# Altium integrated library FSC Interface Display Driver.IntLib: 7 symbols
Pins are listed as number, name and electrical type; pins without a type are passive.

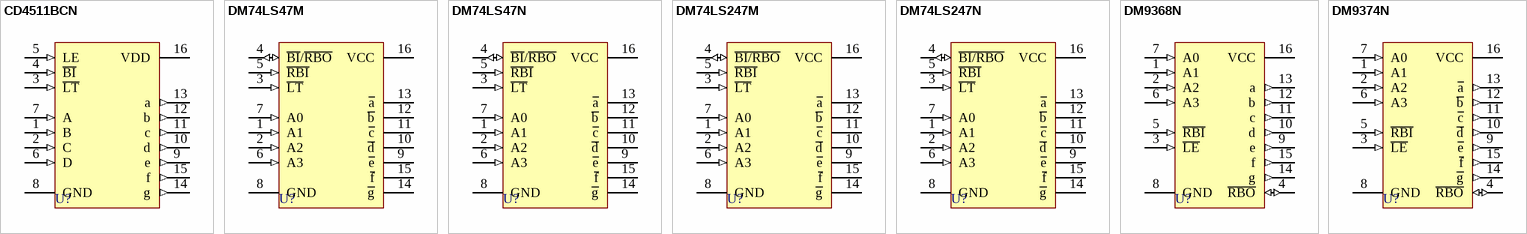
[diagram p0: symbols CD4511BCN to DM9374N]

## CD4511BCN
designator U?
BCD-to-7 Segment Latch/Decoder/Driver
footprint N16E (DIP; 16 Leads; Row Spacing 7.62 mm; Pitch 2.54 mm)
3D model N16E (DIP; 16 Leads; Row Spacing 7.62 mm; Pitch 2.54 mm)
simulation model 4511 (SIMCODE)
pins: 1 B (in), 2 C (in), 3 ~{LT} (in), 4 ~{BI} (in), 5 LE (in), 6 D (in), 7 A (in), 8 GND (power), 9 e (out), 10 d (out), 11 c (out), 12 b (out), 13 a (out), 14 g (out), 15 f (out), 16 VDD (power)

## DM74LS47M
designator U?
BCD to 7-Segment Decoder/Driver with Open-Collector Output
footprint M16A_N (SOIC, 16-Leads, Body 9.9x3.9mm, Pitch 1.27mm, IPC Medium Density)
footprint M16A_L (SOIC, 16-Leads, Body 9.9x3.9mm, Pitch 1.27mm, IPC High Density)
footprint M16A_M (SOIC, 16-Leads, Body 9.9x3.9mm, Pitch 1.27mm, IPC Low Density)
3D model M16A (16-Pin Small Outline Integrated Circuit 1.27 mm Pitch)
signal-integrity model DM74LS47M
pins: 1 A1 (in), 2 A2 (in), 3 ~{LT} (in), 4 ~{BI}/~{RBO} (io), 5 ~{RBI} (in), 6 A3 (in), 7 A0 (in), 8 GND (power), 9 ~{e} (oc), 10 ~{d} (oc), 11 ~{c} (oc), 12 ~{b} (oc), 13 ~{a} (oc), 14 ~{g} (oc), 15 ~{f} (oc), 16 VCC (power)

## DM74LS47N
designator U?
BCD to 7-Segment Decoder/Driver with Open-Collector Output
footprint N16E (DIP; 16 Leads; Row Spacing 7.62 mm; Pitch 2.54 mm)
3D model N16E (DIP; 16 Leads; Row Spacing 7.62 mm; Pitch 2.54 mm)
simulation model 74LS47 (SIMCODE)
signal-integrity model DM74LS47N
pins: 1 A1 (in), 2 A2 (in), 3 ~{LT} (in), 4 ~{BI}/~{RBO} (io), 5 ~{RBI} (in), 6 A3 (in), 7 A0 (in), 8 GND (power), 9 ~{e} (oc), 10 ~{d} (oc), 11 ~{c} (oc), 12 ~{b} (oc), 13 ~{a} (oc), 14 ~{g} (oc), 15 ~{f} (oc), 16 VCC (power)

## DM74LS247M
designator U?
BCD to 7-Segment Decoder/Driver with Open-Collector Output
footprint M16A_N (SOIC, 16-Leads, Body 9.9x3.9mm, Pitch 1.27mm, IPC Medium Density)
footprint M16A_L (SOIC, 16-Leads, Body 9.9x3.9mm, Pitch 1.27mm, IPC High Density)
footprint M16A_M (SOIC, 16-Leads, Body 9.9x3.9mm, Pitch 1.27mm, IPC Low Density)
3D model M16A (16-Pin Small Outline Integrated Circuit 1.27 mm Pitch)
signal-integrity model DM74LS247M
pins: 1 A1 (in), 2 A2 (in), 3 ~{LT} (in), 4 ~{BI/RBO} (io), 5 ~{RBI} (in), 6 A3 (in), 7 A0 (in), 8 GND (power), 9 ~{e} (oc), 10 ~{d} (oc), 11 ~{c} (oc), 12 ~{b} (oc), 13 ~{a} (oc), 14 ~{g} (oc), 15 ~{f} (oc), 16 VCC (power)

## DM74LS247N
designator U?
BCD to 7-Segment Decoder/Driver with Open-Collector Output
footprint N16E (DIP; 16 Leads; Row Spacing 7.62 mm; Pitch 2.54 mm)
3D model N16E (DIP; 16 Leads; Row Spacing 7.62 mm; Pitch 2.54 mm)
simulation model 74LS247 (SIMCODE)
signal-integrity model DM74LS247N
pins: 1 A1 (in), 2 A2 (in), 3 ~{LT} (in), 4 ~{BI/RBO} (io), 5 ~{RBI} (in), 6 A3 (in), 7 A0 (in), 8 GND (power), 9 ~{e} (oc), 10 ~{d} (oc), 11 ~{c} (oc), 12 ~{b} (oc), 13 ~{a} (oc), 14 ~{g} (oc), 15 ~{f} (oc), 16 VCC (power)

## DM9368N
designator U?
7-Segment Decoder/Driver/Latch with Constant Current Source Outputs
footprint N16E (DIP; 16 Leads; Row Spacing 7.62 mm; Pitch 2.54 mm)
3D model N16E (DIP; 16 Leads; Row Spacing 7.62 mm; Pitch 2.54 mm)
pins: 1 A1 (in), 2 A2 (in), 3 ~{LE} (in), 4 ~{RBO} (io), 5 ~{RBI} (in), 6 A3 (in), 7 A0 (in), 8 GND (power), 9 e (out), 10 d (out), 11 c (out), 12 b (out), 13 a (out), 14 g (out), 15 f (out), 16 VCC (power)

## DM9374N
designator U?
7-Segment Decoder/Driver/Latch with Constant Current Sink Outputs
footprint N16E (DIP; 16 Leads; Row Spacing 7.62 mm; Pitch 2.54 mm)
3D model N16E (DIP; 16 Leads; Row Spacing 7.62 mm; Pitch 2.54 mm)
pins: 1 A1 (in), 2 A2 (in), 3 ~{LE} (in), 4 ~{RBO} (io), 5 ~{RBI} (in), 6 A3 (in), 7 A0 (in), 8 GND (power), 9 ~{e} (out), 10 ~{d} (out), 11 ~{c} (out), 12 ~{b} (out), 13 ~{a} (out), 14 ~{g} (out), 15 ~{f} (out), 16 VCC (power)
